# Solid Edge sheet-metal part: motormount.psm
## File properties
Author: ptcarter
Template: normal.psm
Last saved by: ptcarter
Revision: 31
Application: Solid Edge
Accuracy: 0.99
Material Thickness: 2.00 mm
Bend Radius: 1.00 mm
Relief Width: 3.00 mm
Relief Length: 3.00 mm
Neutral Factor: 0.33
Minimum Arc Length: 0.10 mm
Deviational Tolerance: 0.10 mm
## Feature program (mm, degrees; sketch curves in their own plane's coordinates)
base tab "unnamed BaseTab 1"
sketch for "Hole_1" plane through (0, -80, 0) normal (0, -1, 0) x-axis (1, 0, 0)
  hole centre (65, 0) bore radius 2.5
hole "Hole_1"
sketch for "unnamed Hole 1" plane through (0, -80, 0) normal (0, -1, 0) x-axis (1, 0, 0)
  hole centre (-65, 0) bore radius 2.5
hole "unnamed Hole 1"
pattern "unnamed Pattern 1" of "Hole_1", "unnamed Hole 1"
jog tab "JogTab_1"  OffsetDistance = 76 mm
mirror "unnamed Mirror 1" of "JogTab_1" about plane through (0, 0, 0) normal (1, 0, 0)
jog tab "unnamed JogTab 1"
sketch for "unnamed Cutout 1" plane through (0, -80, 0) normal (0, -1, 0) x-axis (1, 0, 0)
extrude "unnamed Cutout 1" cut
break corner "unnamed BreakCorner 1"
extrude "unnamed Cutout 2" cut
break corner "unnamed BreakCorner 2"
sketch for "Hole_3" plane through (0, -80, 0) normal (0, -1, 0) x-axis (1, 0, 0)
hole "Hole_3"
hole "unnamed Hole 2"
hole "unnamed Hole 3"
hole "unnamed Hole 4"
mirror "unnamed Mirror 2" of "unnamed Cutout 1", "unnamed BreakCorner 1" about plane through (0, 0, 0) normal (1, 0, 0)
pattern "unnamed Pattern 3" of "Hole_3"
pattern "unnamed Pattern 2" of "unnamed Pattern 3"
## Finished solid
Body 1: solid body, 80 faces, 208 edges, 120 vertices.
  Faces by surface: cylinder 34, plane 34, spline 12
  Edges by curve: line 132, circle 52, curve on surface 24
Bounding box of the edges (mm; curved faces can reach further): 155.000 x 78.000 x 100.000, from (-77.5, -80, -50) to (77.5, -2, 50).
Cylindrical faces by radius (mm): R1 x16, R2.5 x6, R3 x8, R12.5 x2, R50 x2
Planar faces by outward normal: +x 6, +y 3, +z 2, -x 6, -y 3, -z 2, oblique 12
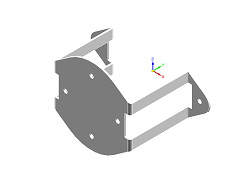
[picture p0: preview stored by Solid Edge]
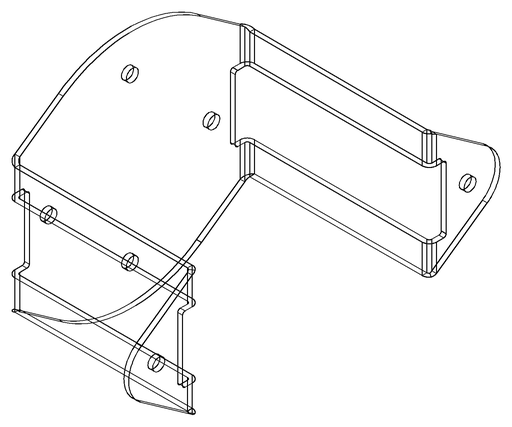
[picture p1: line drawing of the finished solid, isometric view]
